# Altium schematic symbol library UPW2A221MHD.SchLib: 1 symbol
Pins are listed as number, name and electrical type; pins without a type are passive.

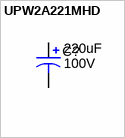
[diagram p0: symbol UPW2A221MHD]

## UPW2A221MHD
designator C?  value 220uF  Value2Displayed: 100V  (hidden comment: UPW2A221MHD)
CAP, AL, 220µF, 100V, +/- 20%, Radial; Manufacturer: Nichicon; Tolerance_%: 20; VDC_V: 100
footprint UPW2A221MHD (16Dx25T-7.5mm LS)
pins: 1 +, 2 -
